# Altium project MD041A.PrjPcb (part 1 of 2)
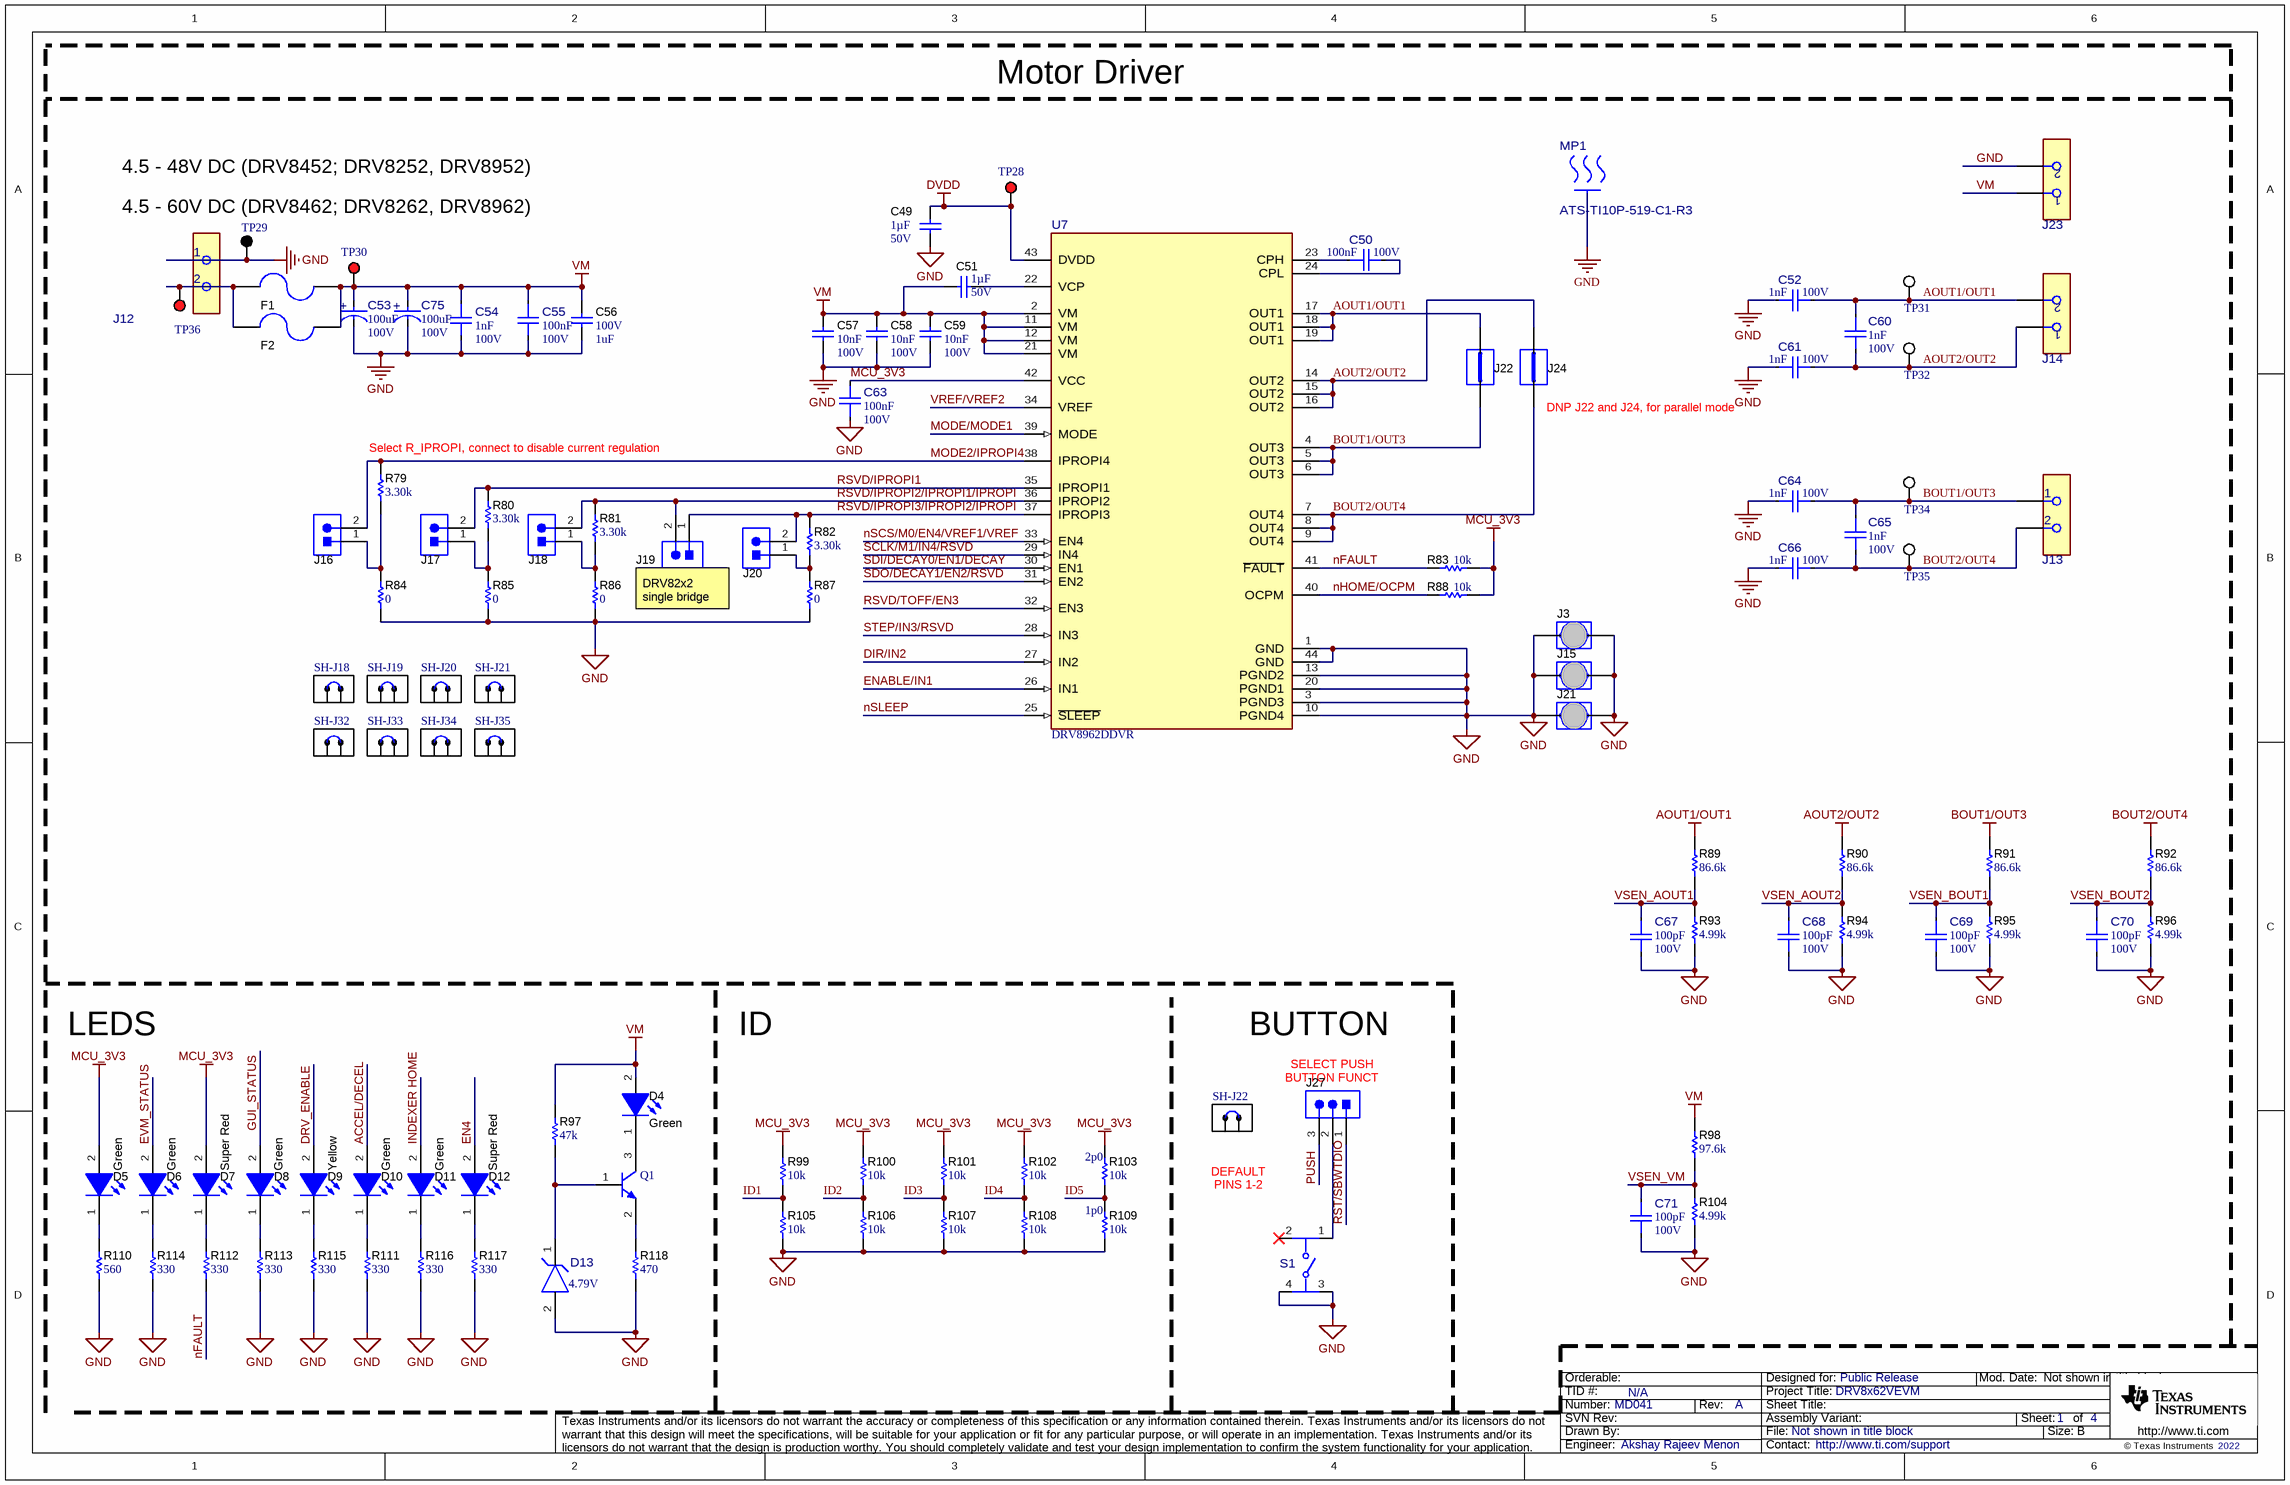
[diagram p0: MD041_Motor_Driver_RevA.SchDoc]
CopyrightYear: 2022; PCB_Layout: Jacob Thompson; PCB_Rev: A; PRJ_Customer: Public Release; PRJ_Engineer: Akshay Rajeev Menon; PRJ_Number: MD041; PRJ_Title: DRV8x62VEVM; SCH_Rev: A; TechSupport: http://www.ti.com/support; TID: N/A
4 sheets, 346 parts. Net scope: global (net labels, ports and power ports of the same name join across sheets).
Board file: MD041A.PcbDoc
Sheets:
  MD041_Motor_Driver_RevA.SchDoc
  MD041_ezFET_RevA.SchDoc
  MD041_Motor_control_RevA.SchDoc
  MD041_Hardware_RevA.SchDoc

## Sheet MD041_Motor_Driver_RevA.SchDoc
size 431 x 279 mm; Date: Not shown in title block; ApprovedBy: Not shown in title block; CheckedBy: Not shown in title block; Author: Not shown in title block; CompanyName: Not shown in title block; Engineer: Not shown in title block; Organization: Not shown in title block; Address1: Not shown in title block; Address2: Not shown in title block; Address3: Not shown in title block; Address4: Not shown in title block; DocumentNumber: 2; Revision: Use project parameter SCH_Rev; SheetNumber: 1; SheetTotal: 4; PageSetup: Record=PageOptions¦CenterHorizontal=True¦CenterVertical=True¦PrintScale=1.00¦XCorrection=1.00¦YCorrection=1.00¦PrintKind=0¦BorderSize=5000000¦LeftOffset=0¦BottomOffset=0¦Orientation=2¦PaperLength=1000¦PaperWidth=1000¦Scale=100¦PaperSource=15¦PrintQuality=600¦MediaType=1¦DitherType=10¦PaperKind=Letter¦PrintScaleMode=1

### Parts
C49  Cap_F: 1µF  VDC_V: 50V  [0805_HV]  (hidden comment: C2012X7R1H105K125AB)
C50  Cap_F: 100nF  VDC_V: 100V  [FP-885012206120_0603-MFG]  (hidden comment: 885012206120)
C51  Cap_F: 1µF  VDC_V: 50V  [0805_HV]  (hidden comment: C2012X7R1H105K125AB)
C52  ValueDisplayed: 1nF  VDC_V: 100V  [FP-885012006085_0603-MFG]  (hidden comment: 885012006085)
C53  ValueDisplayed: 100uF  VDC_V: 100V  [FP-EMVY101ARA101MKE0S_RADIAL-MFG]  (hidden comment: EMVY101ARA101MKE0S)
C54  ValueDisplayed: 1nF  VDC_V: 100V  [FP-885012006085_0603-MFG]  (hidden comment: 885012006085)
C55  Cap_F: 100nF  VDC_V: 100V  [FP-885012206120_0603-MFG]  (hidden comment: 885012206120)
C56  VDC_V: 100V  ValueDisplayed: 1uF  [1210_220]  (hidden comment: CGA6M2X7R2A105K200AA)
C57  Cap_F: 10nF  VDC_V: 100V  [0603L]  (hidden comment: 885012206114)
C58  Cap_F: 10nF  VDC_V: 100V  [0603L]  (hidden comment: 885012206114)
C59  Cap_F: 10nF  VDC_V: 100V  [0603L]  (hidden comment: 885012206114)
C60  ValueDisplayed: 1nF  VDC_V: 100V  [FP-885012006085_0603-MFG]  (hidden comment: 885012006085)
C61  ValueDisplayed: 1nF  VDC_V: 100V  [FP-885012006085_0603-MFG]  (hidden comment: 885012006085)
C63  Cap_F: 100nF  VDC_V: 100V  [FP-885012206120_0603-MFG]  (hidden comment: 885012206120)
C64  ValueDisplayed: 1nF  VDC_V: 100V  [FP-885012006085_0603-MFG]  (hidden comment: 885012006085)
C65  ValueDisplayed: 1nF  VDC_V: 100V  [FP-885012006085_0603-MFG]  (hidden comment: 885012006085)
C66  ValueDisplayed: 1nF  VDC_V: 100V  [FP-885012006085_0603-MFG]  (hidden comment: 885012006085)
C67  ValueDisplayed: 100pF  VDC_V: 100V  [FP-885012005080_0402-MFG]  (hidden comment: 885012005080)
C68  ValueDisplayed: 100pF  VDC_V: 100V  [FP-885012005080_0402-MFG]  (hidden comment: 885012005080)
C69  ValueDisplayed: 100pF  VDC_V: 100V  [FP-885012005080_0402-MFG]  (hidden comment: 885012005080)
C70  ValueDisplayed: 100pF  VDC_V: 100V  [FP-885012005080_0402-MFG]  (hidden comment: 885012005080)
C71  ValueDisplayed: 100pF  VDC_V: 100V  [FP-885012005080_0402-MFG]  (hidden comment: 885012005080)
C75  ValueDisplayed: 100uF  VDC_V: 100V  [FP-EMVY101ARA101MKE0S_RADIAL-MFG]  (hidden comment: EMVY101ARA101MKE0S)
D4  value Green  [WL-SMCW_GREEN]  (hidden comment: 150060VS75000)
D5  value Green  [WL-SMCW_GREEN]  (hidden comment: 150060VS75000)
D6  value Green  [WL-SMCW_GREEN]  (hidden comment: 150060VS75000)
D7  value Super Red  [WL-SMCW_RED]  (hidden comment: 150060SS75000)
D8  value Green  [WL-SMCW_GREEN]  (hidden comment: 150060VS75000)
D9  value Yellow  [WL-SMCW_YELLOW]  (hidden comment: 150060YS75000)
D10  value Green  [WL-SMCW_GREEN]  (hidden comment: 150060VS75000)
D11  value Green  [WL-SMCW_GREEN]  (hidden comment: 150060VS75000)
D12  value Super Red  [WL-SMCW_RED]  (hidden comment: 150060SS75000)
D13  Vf_V: 4.79V  [FP-BZX84J-B4V7,115_SC90-MFG]  (hidden comment: BZX84J-B4V7,115)
F1  0463015.ER  [Fuse_0463]  (value not drawn)
F2  0463015.ER  [Fuse_0463]  (value not drawn)
J3  D3082-05  [Harwin_D3082-05]  (value not drawn)
J12  691256610002  [FP-691256610002_HDR2-MFG]  (value not drawn)
J13  691250610002  [FP-691250610002_CONN_TERM_BLOCK2-MFG]  (value not drawn)
J14  691250610002  [FP-691250610002_CONN_TERM_BLOCK2-MFG]  (value not drawn)
J15  D3082-05  [Harwin_D3082-05]  (value not drawn)
J16  PBC02SAAN  [Sullins_PBC02SAAN]  (value not drawn)
J17  PBC02SAAN  [Sullins_PBC02SAAN]  (value not drawn)
J18  PBC02SAAN  [Sullins_PBC02SAAN]  (value not drawn)
J19  PBC02SAAN  [Sullins_PBC02SAAN]  (value not drawn)
J20  PBC02SAAN  [Sullins_PBC02SAAN]  (value not drawn)
J21  D3082-05  [Harwin_D3082-05]  (value not drawn)
J22  D3082-05  [Harwin_D3082-05]  (value not drawn)
J23  691250610002  [FP-691250610002_CONN_TERM_BLOCK2-MFG]  (value not drawn)
J24  D3082-05  [Harwin_D3082-05]  (value not drawn)
J27  61300311121  [WURTH_61300311121]  (value not drawn)
MP1  ATS-TI10P-519-C1-R3  [FP-ATS-TI10P-519-C1-R3_HEAT_SINK-MFG]
Q1  BC846BLT1G  [ONSC-SOT-23-3-318-08_V]  (value not drawn)
R79  ValueDisplayed: 3.30k  [0402L]  (hidden comment: ERJ-2RKF3301X)
R80  ValueDisplayed: 3.30k  [0402L]  (hidden comment: ERJ-2RKF3301X)
R81  ValueDisplayed: 3.30k  [0402L]  (hidden comment: ERJ-2RKF3301X)
R82  ValueDisplayed: 3.30k  [0402L]  (hidden comment: ERJ-2RKF3301X)
R83  ValueDisplayed: 10k  [0603L]  (hidden comment: RC0603JR-0710KL)
R84  ValueDisplayed: 0  [0402]  (hidden comment: CRCW04020000Z0EDHP)
R85  ValueDisplayed: 0  [0402]  (hidden comment: CRCW04020000Z0EDHP)
R86  ValueDisplayed: 0  [0402]  (hidden comment: CRCW04020000Z0EDHP)
R87  ValueDisplayed: 0  [0402]  (hidden comment: CRCW04020000Z0EDHP)
R88  ValueDisplayed: 10k  [0603L]  (hidden comment: RC0603JR-0710KL)
R89  ValueDisplayed: 86.6k  [0603L]  (hidden comment: CRCW060386K6FKEA)
R90  ValueDisplayed: 86.6k  [0603L]  (hidden comment: CRCW060386K6FKEA)
R91  ValueDisplayed: 86.6k  [0603L]  (hidden comment: CRCW060386K6FKEA)
R92  ValueDisplayed: 86.6k  [0603L]  (hidden comment: CRCW060386K6FKEA)
R93  ValueDisplayed: 4.99k  [0603L]  (hidden comment: CRCW06034K99FKEA)
R94  ValueDisplayed: 4.99k  [0603L]  (hidden comment: CRCW06034K99FKEA)
R95  ValueDisplayed: 4.99k  [0603L]  (hidden comment: CRCW06034K99FKEA)
R96  ValueDisplayed: 4.99k  [0603L]  (hidden comment: CRCW06034K99FKEA)
R97  ValueDisplayed: 47k  [0402]  (hidden comment: CRCW040247K0JNED)
R98  ValueDisplayed: 97.6k  [0603]  (hidden comment: CRCW060397K6FKEA)
R99  ValueDisplayed: 10k  [0603L]  (hidden comment: RC0603JR-0710KL)
R100  ValueDisplayed: 10k  [0603L]  (hidden comment: RC0603JR-0710KL)
R101  ValueDisplayed: 10k  [0603L]  (hidden comment: RC0603JR-0710KL)
R102  ValueDisplayed: 10k  [0603L]  (hidden comment: RC0603JR-0710KL)
R103  ValueDisplayed: 10k  [0603L]  (hidden comment: RC0603JR-0710KL)
R104  ValueDisplayed: 4.99k  [0603L]  (hidden comment: CRCW06034K99FKEA)
R105  ValueDisplayed: 10k  [0603L]  (hidden comment: RC0603JR-0710KL)
R106  ValueDisplayed: 10k  [0603L]  (hidden comment: RC0603JR-0710KL)
R107  ValueDisplayed: 10k  [0603L]  (hidden comment: RC0603JR-0710KL)
R108  ValueDisplayed: 10k  [0603L]  (hidden comment: RC0603JR-0710KL)
R109  ValueDisplayed: 10k  [0603L]  (hidden comment: RC0603JR-0710KL)
R110  ValueDisplayed: 560  [0603]  (hidden comment: RC0603FR-07560RL)
R111  ValueDisplayed: 330  [0603L]  (hidden comment: Resistor)
R112  ValueDisplayed: 330  [0603L]  (hidden comment: Resistor)
R113  ValueDisplayed: 330  [0603L]  (hidden comment: Resistor)
R114  ValueDisplayed: 330  [0603L]  (hidden comment: Resistor)
R115  ValueDisplayed: 330  [0603L]  (hidden comment: Resistor)
R116  ValueDisplayed: 330  [0603L]  (hidden comment: Resistor)
R117  ValueDisplayed: 330  [0603L]  (hidden comment: Resistor)
R118  ValueDisplayed: 470  [0603]  (hidden comment: RC0603FR-07470RL)
S1  430481025816  [FP-430481025816_SMT_SW_6MM2_6MM2-MFG]  (value not drawn)
SH-J18  60900213421  [Wurth_60900213421]  (value not drawn)
SH-J19  60900213421  [Wurth_60900213421]  (value not drawn)
SH-J20  60900213421  [Wurth_60900213421]  (value not drawn)
SH-J21  60900213421  [Wurth_60900213421]  (value not drawn)
SH-J22  60900213421  [Wurth_60900213421]  (value not drawn)
SH-J32  60900213421  [Wurth_60900213421]  (value not drawn)
SH-J33  60900213421  [Wurth_60900213421]  (value not drawn)
SH-J34  60900213421  [Wurth_60900213421]  (value not drawn)
SH-J35  60900213421  [Wurth_60900213421]  (value not drawn)
TP28  5010  [Keystone5010]  (value not drawn)
TP29  5011  [Keystone5011]  (value not drawn)
TP30  5010  [Keystone5010]  (value not drawn)
TP31  5015  [Testpoint_Keystone_Miniature]  (value not drawn)
TP32  5015  [Testpoint_Keystone_Miniature]  (value not drawn)
TP34  5015  [Testpoint_Keystone_Miniature]  (value not drawn)
TP35  5015  [Testpoint_Keystone_Miniature]  (value not drawn)
TP36  5010  [Keystone5010]  (value not drawn)
U7  DRV8962DDVR  [DDV0044E-MFG]

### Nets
AOUT1/OUT1: C52.2 C60.1 J14.2 J22.2 R89.2 TP31.1 U7.17(OUT1) U7.18(OUT1) U7.19(OUT1)
AOUT2/OUT2: C60.2 C61.2 J14.1 J24.2 R90.2 TP32.1 U7.14(OUT2) U7.15(OUT2) U7.16(OUT2)
BOUT1/OUT3: C64.2 C65.1 J13.1 J22.1 R91.2 TP34.1 U7.4(OUT3) U7.5(OUT3) U7.6(OUT3)
BOUT2/OUT4: C65.2 C66.2 J13.2 J24.1 R92.2 TP35.1 U7.7(OUT4) U7.8(OUT4) U7.9(OUT4)
DVDD: C49.2 TP28.1 U7.43(DVDD)
GND: C49.1 C52.1 C53.1(CATHODE) C54.2 C55.2 C56.2 C57.2 C58.2 C59.2 C61.1 C63.1 C64.1 C66.1 C67.2 C68.2 C69.2 C70.2 C71.2 C75.1(CATHODE) D13.2(anode) J3.1 J3.2 J12.1 J15.1 J15.2 J21.1 J21.2 J23.2 R84.1 R85.1 R86.1 R87.1 R93.1 R94.1 R95.1 R96.1 R104.1 R105.2 R106.2 R107.2 R108.2 R109.2 R110.1 R111.1 R113.1 R114.1 R115.1 R116.1 R117.1 R118.1 S1.3 S1.4 TP29.1 U7.1(GND) U7.3(PGND3) U7.10(PGND4) U7.13(PGND2) U7.20(PGND1) U7.44(GND)
MCU_3V3: C63.2 D5.2(A) D7.2(A) R83.2 R88.2 R99.1 R100.1 R101.1 R102.1 R103.1 U7.42(VCC)
VM: C51.2 C53.2(ANODE) C54.1 C55.1 C56.1 C57.1 C58.1 C59.1 C75.2(ANODE) D4.2(A) F1.1 F2.1 J23.1 R97.2 R98.2 TP30.1 U7.2(VM) U7.11(VM) U7.12(VM) U7.21(VM)
ACCEL/DECEL: D10.2(A)
DIR/IN2: U7.27(IN2)
DRV_ENABLE: D9.2(A)
EN4: D12.2(A)
ENABLE/IN1: U7.26(IN1)
EVM_STATUS: D6.2(A)
GUI_STATUS: D8.2(A)
ID1: R99.2 R105.1
ID2: R100.2 R106.1
ID3: R101.2 R107.1
ID4: R102.2 R108.1
ID5: R103.2 R109.1
INDEXER HOME: D11.2(A)
MODE2/IPROPI4: J16.2 R79.2 U7.38(IPROPI4)
MODE/MODE1: U7.39(MODE)
nFAULT: R83.1 R112.1 U7.41(~{FAULT})
nHOME/OCPM: R88.1 U7.40(OCPM)
nSCS/M0/EN4/VREF1/VREF: U7.33(EN4)
nSLEEP: U7.25(~{SLEEP})
PUSH: J27.3
RST/SBWTDIO: J27.1
RSVD/IPROPI1: J17.2 R80.2 U7.35(IPROPI1)
RSVD/IPROPI2/IPROPI1/IPROPI: J18.2 J19.2 R81.2 U7.36(IPROPI2)
RSVD/IPROPI3/IPROPI2/IPROPI: J19.1 J20.2 R82.2 U7.37(IPROPI3)
RSVD/TOFF/EN3: U7.32(EN3)
SCLK/M1/IN4/RSVD: U7.29(IN4)
SDI/DECAY0/EN1/DECAY: U7.30(EN1)
SDO/DECAY1/EN2/RSVD: U7.31(EN2)
STEP/IN3/RSVD: U7.28(IN3)
VREF/VREF2: U7.34(VREF)
VSEN_AOUT1: C67.1 R89.1 R93.2
VSEN_AOUT2: C68.1 R90.1 R94.2
VSEN_BOUT1: C69.1 R91.1 R95.2
VSEN_BOUT2: C70.1 R92.1 R96.2
VSEN_VM: C71.1 R98.1 R104.2
NetC50_1: C50.1 U7.23(CPH)
NetC50_2: C50.2 U7.24(CPL)
NetC51_1: C51.1 U7.22(VCP)
NetD4_1: D4.1(K) Q1.3(C)
NetD5_1: D5.1(K) R110.2
NetD6_1: D6.1(K) R114.2
NetD7_1: D7.1(K) R112.2
NetD8_1: D8.1(K) R113.2
NetD9_1: D9.1(K) R115.2
NetD10_1: D10.1(K) R111.2
NetD11_1: D11.1(K) R116.2
NetD12_1: D12.1(K) R117.2
NetD13_1: D13.1(cathode) Q1.1(B) R97.1
NetF1_2: F1.2 F2.2 J12.2 TP36.1
NetJ16_1: J16.1 R79.1 R84.2
NetJ17_1: J17.1 R80.1 R85.2
NetJ18_1: J18.1 R81.1 R86.2
NetJ20_1: J20.1 R82.1 R87.2
NetJ27_2: J27.2 S1.1
NetQ1_2: Q1.2(E) R118.2

Not connected (* = marked no-connect by the designer): S1 2*

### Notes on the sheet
- Motor Driver
- 4.5 - 48V DC (DRV8452; DRV8252, DRV8952)
- 4.5 - 60V DC (DRV8462; DRV8262, DRV8962)
- (near J24) DNP J22 and J24, for parallel mode
- (near R79) Select R_IPROPI, connect to disable current regulation
- DRV82x2 single bridge
- LEDS
- ID
- BUTTON
- (near J27) SELECT PUSH
- (near J27) BUTTON FUNCT
- (near R103) 2p0
- (near SH-J22) DEFAULT
- (near R109) 1p0
- PINS 1-2

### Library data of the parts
C49 C51 = CMP-0007873-2: CAP, CERM, 1 uF, 50 V, +/- 10%, X7R, 0805; Manufacturer: TDK; TaMin_C: -55°C; ESR_ohm: 8.782m; Polarized: N; SizeAreaWB_mm2: 6.75; Value1: 0.008782 ohm; U/M: EA; Value: 1uF; TaMax_C: 125°C; SizeZ_mm: 1.45; SizeX_mm: 2; SizeY_mm: 1.25; Cap_Case: 0805; SizeArea_mm2: 2.5; IRMS_A: 2.2049A; AEC Category: Q200
C50 C55 C63 = CMP-0095152-1: 0.1 µF ±10% 100V Ceramic Capacitor X7R 0603 (1608 Metric); Manufacturer: Wurth Electronics; Value: 100nF; SizeZ_mm: 0.87mm; AEC Qualified: No; TempCo: 15%
C52 C54 C60 C61 C64-C66 = CMP-0097311-1: 1000 pF ±5% 100V Ceramic Capacitor C0G, NP0 0603 (1608 Metric); Manufacturer: Wurth Electronics; TempCo: 30ppm/°C; SizeZ_mm: 0.87mm; AEC Qualified: No; Value: 1nF
C53 C75 = CMP-0094051-1: 100uF 100V 20% Aluminum Electrolytic Capacitors Radial, Can - SMD - 5000 Hrs @ 105°C; Manufacturer: United Chemi-Con; Value: 100µF; IRMS_A: 450mA; Life: 5000Hours; SizeZ_mm: 14mm; AEC Grade: Grade 2; Leakage Current: 100uA; Dissipation Factor: 10%; AEC Qualified: Yes
C56 = CMP-0009145-2: CAP, CERM, 1 uF, 100 V, +/- 10%, X7R, AEC-Q200 Grade 1, 1210; Manufacturer: TDK; TaMin_C: -55°C; ESR_ohm: 4.956m; Polarized: N; SizeAreaWB_mm2: 14.7; Value1: 0.004956 ohm; U/M: EA; Value: 1uF; TaMax_C: 125°C; SizeZ_mm: 2.2; SizeX_mm: 3.2; SizeY_mm: 2.5; SizeArea_mm2: 8; AEC Qualified: Y; Cap_F: 1µF; IRMS_A: 3.3073A; AEC Grade: 1; AEC Category: Q200
C57-C59 = CMP-0079993-1: CAP, CERM, 0.01 µF, 100 V,+/- 10%, X7R, 0603; Manufacturer: Wurth Elektronik; Polarized: N; Value: 0.01uF; ValueDisplayed: 0.01µF; U/M: EA; TaMin_C: -55°C; TaMax_C: 105°C; Cap_Case: 0603; SizeX_mm: 1.6; SizeArea_mm2: 1.28; AEC Category: Q200; SizeZ_mm: 1; SizeAreaWB_mm2: 4.68; SizeY_mm: 0.8
C67-C71 = CMP-0097308-1: 100 pF ±5% 100V Ceramic Capacitor C0G, NP0 0402 (1005 Metric); Manufacturer: Wurth Electronics; Value: 100pF; SizeZ_mm: 0.55mm; TempCo: 30ppm/°C; AEC Qualified: No
D4-D6 D8 D10 D11 = CMP-0002894-2: LED, Green, SMD; Manufacturer: Wurth Elektronik; Type: AlInGaP; Value2: 2V; Io_A: 20mA; Value1: W
D7 D12 = CMP-0002893-1: LED, Super Red, SMD; Manufacturer: Wurth Elektronik; Io_A: 20mA; Value1: W; U/M: EA; Vf_V: 1.9V; Type: AlInGaP
D9 = CMP-0002892-3: LED, Yellow, SMD; Manufacturer: Wurth Elektronik; Value1: W; Vf_V: 2V; Type: AlInGaP; Io_A: 20mA
D13 = CMP-0097377-1: Diode Zener Single 4.7V 2% 550mW Automotive 2-Pin SOD-323F T/R; Manufacturer: Nexperia; TaMin_C: -55°C; Vr_V: 2V; SizeZ_mm: 0.8mm; Max Reverse Leakage Current: 3uA; TJmax_C: 150°C; Zener Impedance: 80Ω; AEC Grade: Grade 0; Forward Current: 250mA; TaMax_C: +150°C; AEC Qualified: Yes
F1 F2 = CMP-0081016-1: Fuse, 15 A, 250 VAC, 100 VDC, SMD; Manufacturer: Littelfuse; TaMin_C: -55°C; Irating_A: 15A; SizeAreaWB_mm2: 61.952; Interrupt_AC: 100A; Interrupt_DC: 50A; VAC_V: 250V; TaMax_C: 125°C; Fuse Speed: Fast; SizeZ_mm: 3.12; SizeX_mm: 10.1; SizeArea_mm2: 31.512; VDC_V: 100V; Fuse Technology: Board Mount; Rtyp_Ohm: 4.7m; MeltingTyp: 142
J3 J15 J21 J22 J24 = CMP-0075110-1: 1mm Uninsulated Shorting Plug, 10.16mm spacing, TH; Manufacturer: Harwin; CNHeader: False; Green_Lifecycle: Active; Green_REACh: Passed; CompType: Jumper Wire
J12 = CMP-0086764-1: 2 Position Wire to Board Terminal Block Horizontal with Board 0.400" (10.16mm) Through Hole; Manufacturer: Wurth; Current_A: 57A; Voltage_V: 750V; ContactFinish: Zinc; Row_Count: 1
J13 J14 J23 = CMP-0093233-2: 2 Position Wire to Board Terminal Block Horizontal with Board 0.250" (6.35mm) Through Hole; Manufacturer: Wurth Electronics; Current_A: 32A; Conn Gender: Female; Row_Count: 1; ContactFinish: Zinc; SizeZ_mm: 21.6mm; Max Wire Gauge: 10; Min Wire Gauge: 30; Voltage_V: 450V; AEC Qualified: No; Is Female: yes
J16-J20 = CMP-0054566-1: Header, 100mil, 2x1, Gold, TH; Manufacturer: Sullins Connector Solutions; CNHeader: TRUE; Current_A: 3A; Green_Lifecycle: Active; Shrouded: N; Gender: Male; Green_REACh: Passed; Voltage_V: 1.8kV; Row_Count: 1; Pitch_mm: 2.54; CT: FALSE; Cert_UL: Y
J27 = CMP-0054796-4: Header, 2.54 mm, 3x1, Gold, TH; Manufacturer: Wurth Elektronik; Green_Lifecycle: Active; Green_REACh: Passed; CT: FALSE; CNHeader: TRUE
MP1 = CMP-0096184-1: Heat Sink Aluminum Top Mount; Manufacturer: Advanced Thermal Solutions; AEC Qualified: No; Thermal Resistance Forced Air Flow: 2.2°C/W; SizeZ_mm: 35.6mm; Standoff Height: 1.6mm
Q1 = CMP-1048-00779-1: General Purpose Transistor, NPN Silicon, 3-Pin SOT-23, Pb-Free, Tape and Reel; Manufacturer: On Semiconductor; fT Min (MHz): 100; IC Continuous (A): 0.1
R79-R82 = CMP-0026695-1: RES, 3.30 k, 1%, 0.1 W, AEC-Q200 Grade 0, 0402; Manufacturer: Panasonic; Power_W: 100mW; TempCo: 100 ppm/C; Value_Code: 3k30; U/M: EA; Value: 3.30k; Res_ohm: 3.3k; SizeX_mm: 1; SizeY_mm: 0.5; SizeZ_mm: 0.6; Value2: 0.1W; AEC Qualified: Y; VDC_V: 50V; AEC Grade: 0; AEC Category: Q200
R83 R88 R99-R103 R105-R109 = CMP-0025886-5: RES, 10 k, 5%, 0.1 W, 0603; Manufacturer: Yageo; Power_W: 100mW; TempCo: 100 ppm/C; Value_Code: 10k0; Value: 10k; EIA_Code: E24; SizeX_mm: 1.6; SizeY_mm: 0.8; SizeZ_mm: 1; Value2: 0.1W; SizeArea_mm2: 1.28; AEC Qualified: N; VDC_V: 75V; AEC Category: Q200; SizeAreaWB_mm2: 4.68
R84-R87 = CMP-0081856-1: RES, 0, 0%, 0.2 W, AEC-Q200 Grade 0, 0402; Manufacturer: Vishay-Dale; SizeAreaWB_mm2: 3; SizeArea_mm2: 0.5; AEC Qualified: Y; AEC Category: Q200; Value: 0; SizeZ_mm: 0.6; Power_W: 200mW; VDC_V: 50V; Value2: 0.2W; SizeX_mm: 1
R89-R92 = CMP-0022628-4: RES, 86.6 k, 1%, 0.1 W, AEC-Q200 Grade 0, 0603; Manufacturer: Vishay-Dale; Value: 86.6k; Value_Code: 86k6; Power_W: 100mW; Value2: 0.1W; VDC_V: 75V; TempCo: 100 ppm/C; EIA_Code: E96; AEC Category: Q200; AEC Qualified: Y; AEC Grade: 0; SizeY_mm: 0.8; SizeZ_mm: 1; SizeArea_mm2: 1.28; SizeX_mm: 1.6
R93-R96 R104 = CMP-0022458-4: RES, 4.99 k, 1%, 0.1 W, AEC-Q200 Grade 0, 0603; Manufacturer: Vishay-Dale; Value: 4.99k; Value_Code: 4k99; Power_W: 100mW; Value2: 0.1W; VDC_V: 75V; TempCo: 100 ppm/C; EIA_Code: E96; SizeX_mm: 1.6; SizeY_mm: 0.8; SizeZ_mm: 1; SizeArea_mm2: 1.28; AEC Qualified: Y; AEC Category: Q200; AEC Grade: 0
R97 = CMP-0026935-3: RES, 47 k, 5%, 0.063 W, AEC-Q200 Grade 0, 0402; Manufacturer: Vishay-Dale; Power_W: 63mW; TempCo: 200 ppm/C; Value_Code: 47k0; Value: 47k; EIA_Code: E24; SizeX_mm: 1; SizeY_mm: 0.5; SizeZ_mm: 0.6; Value2: 0.063W; AEC Qualified: Y; VDC_V: 50V; AEC Category: Q200; AEC Grade: 0
R98 = CMP-0022663-4: RES, 97.6 k, 1%, 0.1 W, AEC-Q200 Grade 0, 0603; Manufacturer: Vishay-Dale; Value: 97.6k; Value_Code: 97k6; Power_W: 100mW; Value2: 0.1W; VDC_V: 75V; TempCo: 100 ppm/C; EIA_Code: E96; AEC Category: Q200; AEC Qualified: Y; AEC Grade: 0; SizeY_mm: 0.8; SizeZ_mm: 1; SizeArea_mm2: 1.28; SizeX_mm: 1.6
R110 = CMP-0023183-5: RES, 560, 1%, 0.1 W, 0603; Manufacturer: Yageo; Power_W: 100mW; TempCo: 100 ppm/C; Value_Code: 560R; Value: 560; SizeX_mm: 1.6; SizeY_mm: 0.8; SizeZ_mm: 1; Value2: 0.1W; SizeArea_mm2: 1.28; AEC Qualified: N; VDC_V: 75V; AEC Category: Q200; SizeAreaWB_mm2: 4.68
R111-R117 = CMP-0025785-4: RES, 330, 5%, 0.1 W, AEC-Q200 Grade 0, 0603; PartNumber: CRCW0603330RJNEA; Manufacturer: Vishay-Dale; Value: 330; Value_Code: 330R; Power_W: 100mW; Value2: 0.1W; VDC_V: 75V; TempCo: 200 ppm/C; EIA_Code: E24; AEC Category: Q200; AEC Qualified: Y; AEC Grade: 0; SizeX_mm: 1.6; SizeY_mm: 0.8; SizeZ_mm: 1; SizeArea_mm2: 1.28
R118 = CMP-0023129-5: RES, 470, 1%, 0.1 W, 0603; Manufacturer: Yageo; Power_W: 100mW; TempCo: 100 ppm/C; Value_Code: 470R; Value: 470; SizeX_mm: 1.6; SizeY_mm: 0.8; SizeZ_mm: 1; Value2: 0.1W; SizeArea_mm2: 1.28; AEC Qualified: N; VDC_V: 75V; AEC Category: Q200; SizeAreaWB_mm2: 4.68
S1 = CMP-0097347-1: Tactile Switch SPST-NO Top Actuated Surface Mount; Manufacturer: Wurth Electronics; VDC_V: 12V; Electromechanical Life: 1000000Cycles; SizeZ_mm: 2.7mm; Coil Resistance_ohm: 100mΩ; Operating Force: 160gf; AEC Qualified: No; Contact Current Rating: 50mA
SH-J18-SH-J22 SH-J32-SH-J35 = CMP-0003761-2: Shunt, 2.54mm, Gold, Black; Manufacturer: Wurth Elektronik
TP28 TP30 TP36 = CMP-0055147-2: Test Point, Multipurpose, Red, TH; Manufacturer: Keystone Electronics; CNHeader: FALSE; Green_Lifecycle: Active; Green_REACh: Passed; ContactFinish: Silver; CT: TRUE
TP29 = CMP-0055148-2: Test Point, Multipurpose, Black, TH; Manufacturer: Keystone Electronics; CNHeader: FALSE; Green_Lifecycle: Active; Green_REACh: Passed; ContactFinish: Silver; CT: TRUE
TP31 TP32 TP34 TP35 = CMP-0055152-2: Test Point, Miniature, SMT; Manufacturer: Keystone Electronics; CNHeader: FALSE; Green_Lifecycle: Active; Green_REACh: Passed; CT: TRUE
U7 = CMP-0094088-3: Quad Half-Bridge Motor Driver with Current Sense Output; Manufacturer: Texas Instruments; Standoff Height: 0.05mm; AEC Qualified: No; CompType: IC; Motor Type: Stepper; SizeZ_mm: 1.2mm; Min Supply Voltage: 4.5V; TaMax_C: +125°C; TaMin_C: -40°C; Max Supply Voltage: 60V; Number Of Outputs: 4; Nominal Supply Current: 3-7mA; TJmax_C: +150°C; Switching Frequency: 360kHz; AEC Category: Q200

## Sheet MD041_ezFET_RevA.SchDoc
size 431 x 279 mm; Date: Not shown in title block; ApprovedBy: Not shown in title block; CheckedBy: Not shown in title block; Author: Not shown in title block; CompanyName: Not shown in title block; Engineer: Not shown in title block; Organization: Not shown in title block; Address1: Not shown in title block; Address2: Not shown in title block; Address3: Not shown in title block; Address4: Not shown in title block; DocumentNumber: 2; Revision: Use project parameter SCH_Rev; SheetNumber: 2; SheetTotal: 4; PageSetup: Record=PageOptions¦CenterHorizontal=True¦CenterVertical=True¦PrintScale=1.00¦XCorrection=1.00¦YCorrection=1.00¦PrintKind=0¦BorderSize=5000000¦LeftOffset=0¦BottomOffset=0¦Orientation=2¦PaperLength=1000¦PaperWidth=1000¦Scale=100¦PaperSource=15¦PrintQuality=600¦MediaType=1¦DitherType=10¦PaperKind=Letter¦PrintScaleMode=1
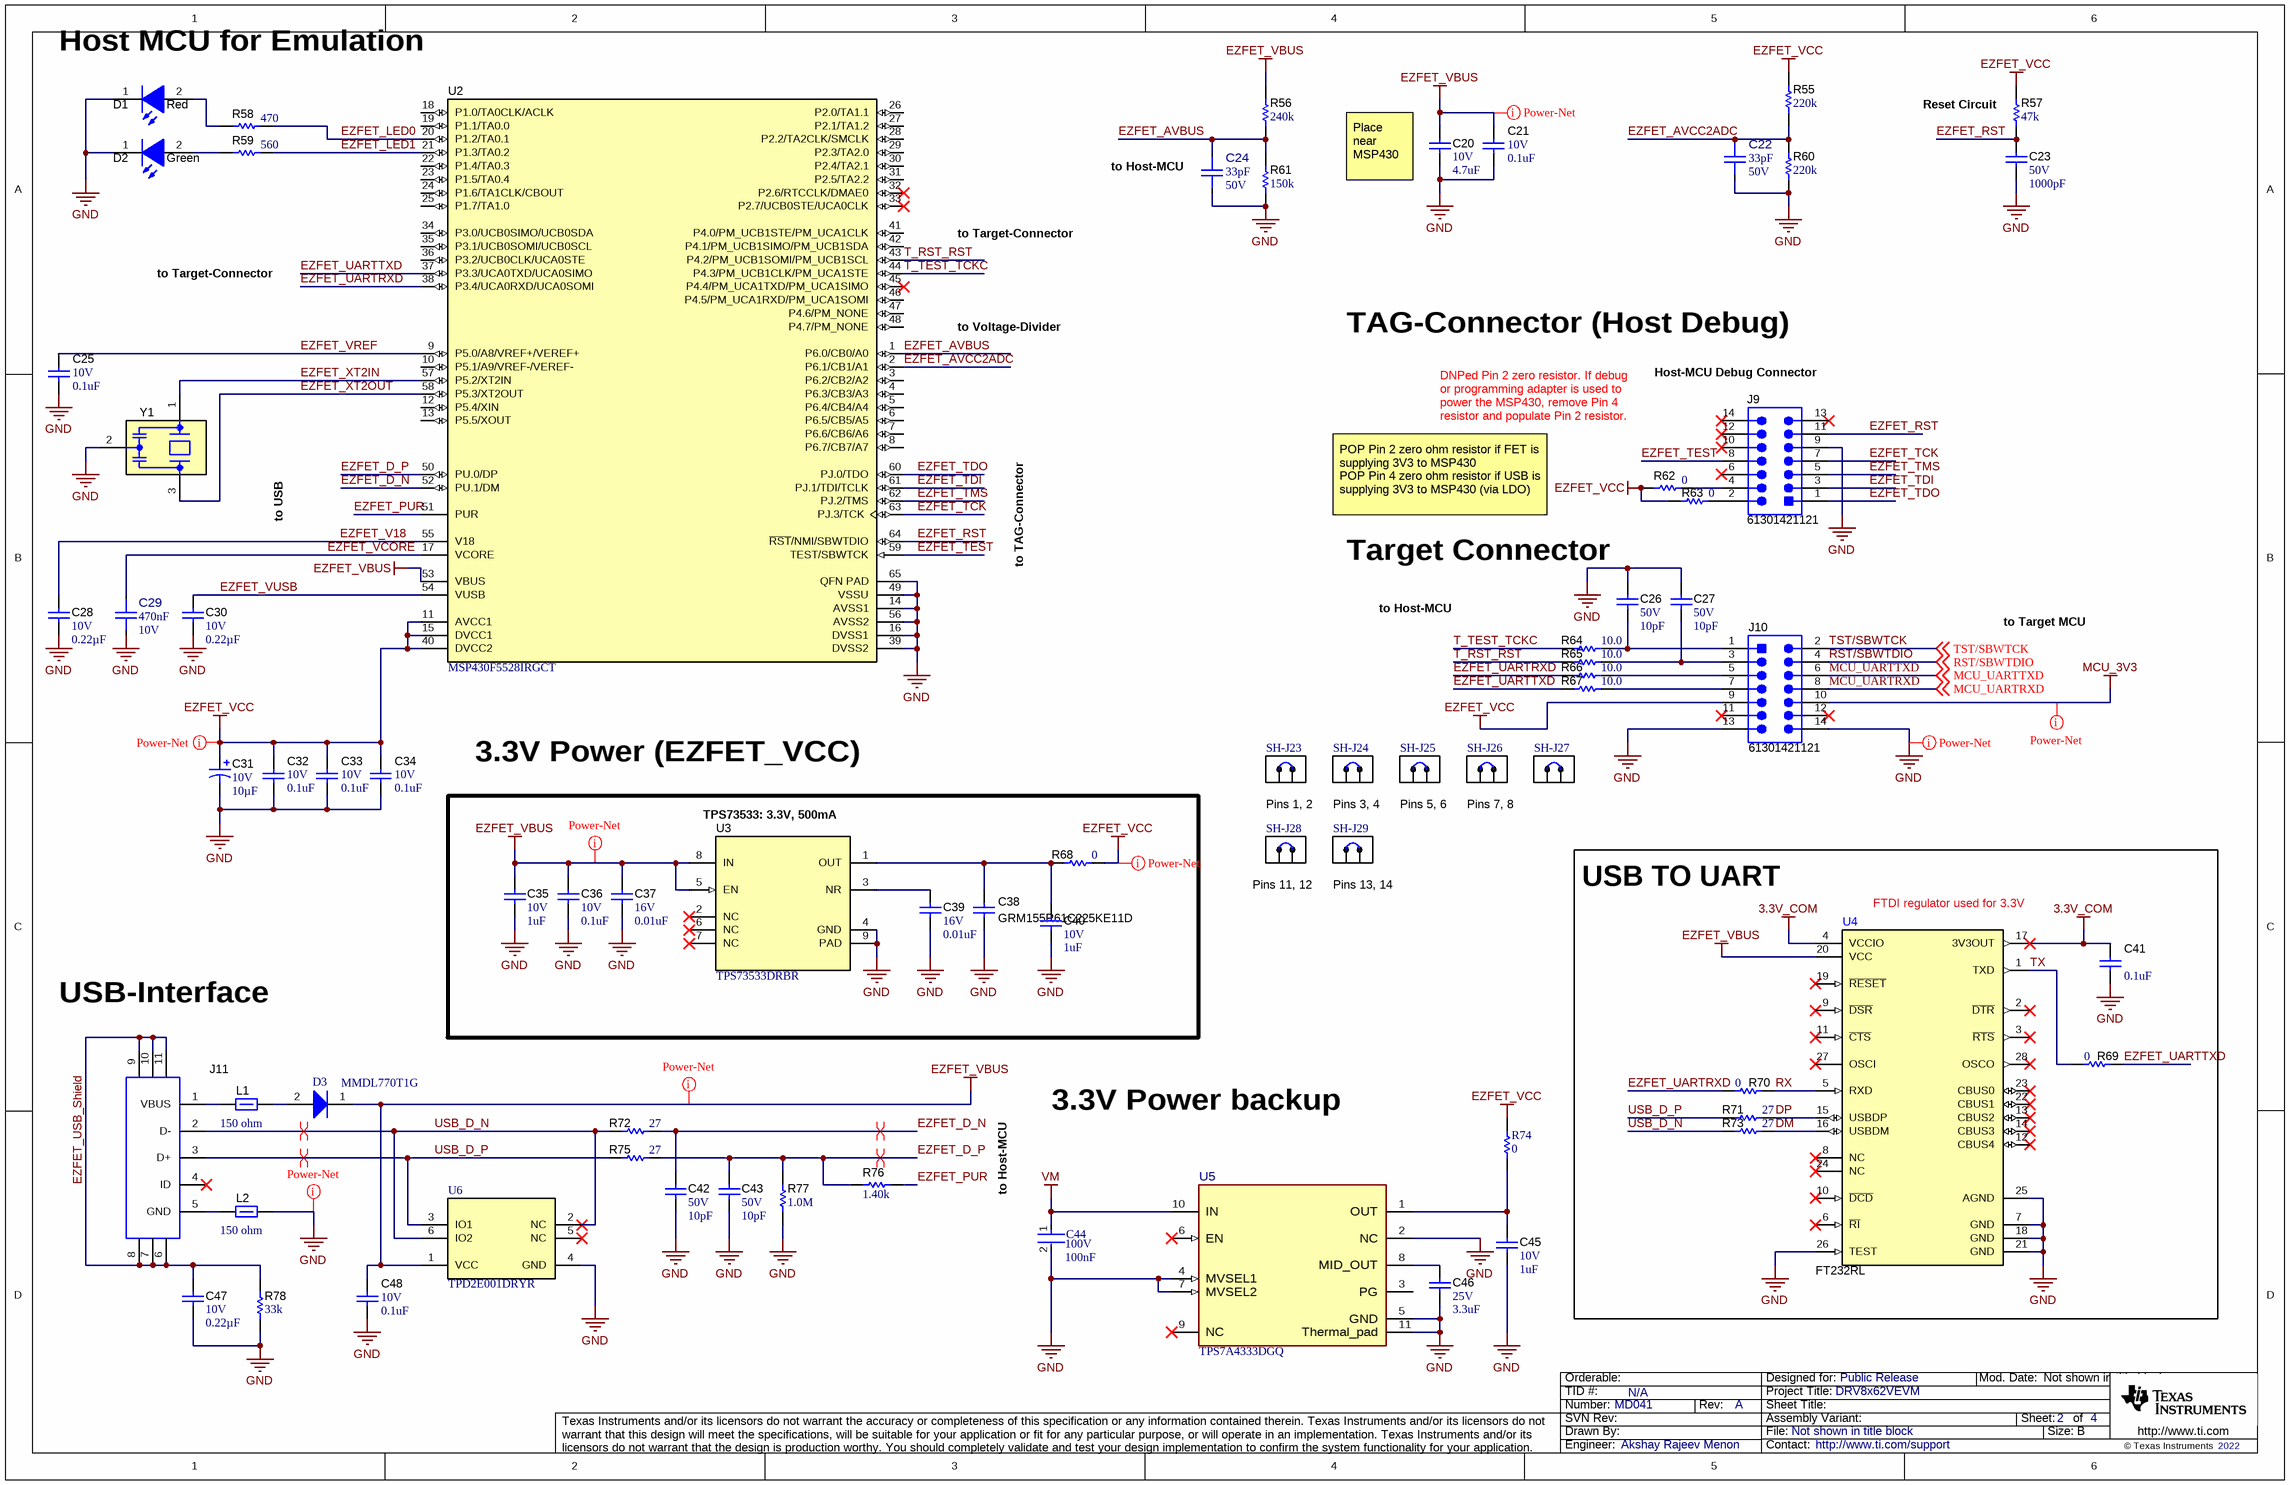
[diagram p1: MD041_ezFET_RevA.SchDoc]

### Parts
C20  VDC_V: 10V  ValueDisplayed: 4.7uF  [0402]  (hidden comment: C1005X5R1A475M050BC)
C21  VDC_V: 10V  ValueDisplayed: 0.1uF  [0402]  (hidden comment: 885012105010)
C22  ValueDisplayed: 33pF  VDC_V: 50V  [FP-885012005058_0402-MFG]  (hidden comment: 885012005058)
C23  VDC_V: 50V  ValueDisplayed: 1000pF  [0402]  (hidden comment: 885012205061)
C24  ValueDisplayed: 33pF  VDC_V: 50V  [FP-885012005058_0402-MFG]  (hidden comment: 885012005058)
C25  VDC_V: 10V  ValueDisplayed: 0.1uF  [0402]  (hidden comment: 885012105010)
C26  VDC_V: 50V  ValueDisplayed: 10pF  [0402]  (hidden comment: 885012005055)
C27  VDC_V: 50V  ValueDisplayed: 10pF  [0402]  (hidden comment: 885012005055)
C28  VDC_V: 10V  ValueDisplayed: 0.22µF  [0402]  (hidden comment: 885012105011)
C29  ValueDisplayed: 470nF  VDC_V: 10V  [FP-885012106008_0603-MFG]  (hidden comment: 885012106008)
C30  VDC_V: 10V  ValueDisplayed: 0.22µF  [0402]  (hidden comment: 885012105011)
C31  VDC_V: 10V  ValueDisplayed: 10µF  [3216-18]  (hidden comment: T520A106M010ATE080)
C32  VDC_V: 10V  ValueDisplayed: 0.1uF  [0402]  (hidden comment: 885012105010)
C33  VDC_V: 10V  ValueDisplayed: 0.1uF  [0402]  (hidden comment: 885012105010)
C34  VDC_V: 10V  ValueDisplayed: 0.1uF  [0402]  (hidden comment: 885012105010)
C35  VDC_V: 10V  ValueDisplayed: 1uF  [0402]  (hidden comment: 885012105012)
C36  VDC_V: 10V  ValueDisplayed: 0.1uF  [0402]  (hidden comment: GRM155R61A104KA01D)
C37  VDC_V: 16V  ValueDisplayed: 0.01uF  [0402]  (hidden comment: GRM155R71C103KA01D)
C38  GRM155R61C225KE11D  [0402]
C39  VDC_V: 16V  ValueDisplayed: 0.01uF  [0402]  (hidden comment: GRM155R71C103KA01D)
C40  VDC_V: 10V  ValueDisplayed: 1uF  [0402]  (hidden comment: 885012105012)
C41  ValueDisplayed: 0.1uF  [0402]  (hidden comment: 885012105010)
C42  VDC_V: 50V  ValueDisplayed: 10pF  [0402]  (hidden comment: 885012005055)
C43  VDC_V: 50V  ValueDisplayed: 10pF  [0402]  (hidden comment: 885012005055)
C44  Voltage Rating: 100V  Capacitance: 100nF  [FP-0603-L_1_6_0_1-W_0_8_0-IPC_B]  (hidden comment: HMK107BJ104MA-T)
C45  VDC_V: 10V  ValueDisplayed: 1uF  [0402]  (hidden comment: 885012105012)
C46  VDC_V: 25V  ValueDisplayed: 3.3uF  [0805_HV]  (hidden comment: GRM21BC81E335KA73L)
C47  VDC_V: 10V  ValueDisplayed: 0.22µF  [0402]  (hidden comment: 885012105011)
C48  VDC_V: 10V  ValueDisplayed: 0.1uF  [0402]  (hidden comment: 885012105010)
D1  value Red  [WL-SMCW_RED]  (hidden comment: 150060RS75000)
D2  value Green  [WL-SMCW_GREEN]  (hidden comment: 150060VS75000)
D3  MMDL770T1G  [ONSC-SOD-323-2-477-02_V]
J9  61301421121  [Wurth_61301421121]
J10  61301421121  [Wurth_61301421121]
J11  1051640001  [Molex_1051640001]  (value not drawn)
L1  value 150 ohm  [0603]  (hidden comment: BLM18AG151BH1D)
L2  ValueDisplayed: 150 ohm  [0603]  (hidden comment: BLM18AG151BH1D)
R55  ValueDisplayed: 220k  [0402]  (hidden comment: RC0402FR-07220KL)
R56  ValueDisplayed: 240k  [0402]  (hidden comment: CRCW0402240KFKED)
R57  ValueDisplayed: 47k  [0402]  (hidden comment: CRCW040247K0JNED)
R58  ValueDisplayed: 470  [0402]  (hidden comment: CRCW0402470RJNED)
R59  ValueDisplayed: 560  [0402]  (hidden comment: CRCW0402560RJNED)
R60  ValueDisplayed: 220k  [0402]  (hidden comment: RC0402FR-07220KL)
R61  ValueDisplayed: 150k  [0402]  (hidden comment: CRCW0402150KFKED)
R62  value 0  [0402L]  (hidden comment: ERJ-2GE0R00X)
R63  value 0  [0402L]  (hidden comment: ERJ-2GE0R00X)
R64  ValueDisplayed: 10.0  [0402]  (hidden comment: CRCW040210R0FKED)
R65  ValueDisplayed: 10.0  [0402]  (hidden comment: CRCW040210R0FKED)
R66  ValueDisplayed: 10.0  [0402]  (hidden comment: CRCW040210R0FKED)
R67  ValueDisplayed: 10.0  [0402]  (hidden comment: CRCW040210R0FKED)
R68  value 0  [0402L]  (hidden comment: Resistor)
R69  value 0  [0603L]  (hidden comment: Resistor)
R70  value 0  [0603L]  (hidden comment: Resistor)
R71  ValueDisplayed: 27  [0402]  (hidden comment: CRCW040227R0JNED)
R72  ValueDisplayed: 27  [0402]  (hidden comment: CRCW040227R0JNED)
R73  ValueDisplayed: 27  [0402]  (hidden comment: CRCW040227R0JNED)
R74  0  [RESC1005X40X25NL05T05]
R75  ValueDisplayed: 27  [0402]  (hidden comment: CRCW040227R0JNED)
R76  ValueDisplayed: 1.40k  [0402]  (hidden comment: CRCW04021K40FKED)
R77  ValueDisplayed: 1.0M  [0402]  (hidden comment: CRCW04021M00JNED)
R78  ValueDisplayed: 33k  [0402]  (hidden comment: CRCW040233K0JNED)
SH-J23  60900213421  [Wurth_60900213421]  (value not drawn)
SH-J24  60900213421  [Wurth_60900213421]  (value not drawn)
SH-J25  60900213421  [Wurth_60900213421]  (value not drawn)
SH-J26  60900213421  [Wurth_60900213421]  (value not drawn)
SH-J27  60900213421  [Wurth_60900213421]  (value not drawn)
SH-J28  60900213421  [Wurth_60900213421]  (value not drawn)
SH-J29  60900213421  [Wurth_60900213421]  (value not drawn)
U2  MSP430F5528IRGCT  [RGC0064B]
U3  TPS73533DRBR  [DRB0008A]
U4  FT232RL  [SSOP28_N]
U5  TPS7A4333DGQ  [DGQ0010E-MFG]
U6  TPD2E001DRYR  [DRY0006A]
Y1  CSTNR4M00GH5L000R0  [MuRata_CSTNR]  (value not drawn)

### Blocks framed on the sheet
TPS73533: 3.3V, 500mA: C35-C40 R68 U3
USB TO UART: C41 R69-R71 R73 U4

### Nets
3.3V_COM: C41.1 U4.4(VCCIO) U4.17(3V3OUT)
EZFET_VBUS: C20.1 C21.1 C35.1 C36.1 C37.1 C48.1 D3.1(K) R56.2 U2.53(VBUS) U3.5(EN) U3.8(IN) U4.20(VCC) U6.1(VCC)
EZFET_VCC: C31.1(+) C32.1 C33.1 C34.1 J10.9 R55.2 R57.2 R62.1 R63.1 R68.2 R74.2 U2.11(AVCC1) U2.15(DVCC1) U2.40(DVCC2)
GND: C20.2 C21.2 C22.2 C23.2 C24.2 C25.2 C26.1 C27.1 C28.2 C29.2 C30.2 C31.2(-) C32.2 C33.2 C34.2 C35.2 C36.2 C37.2 C38.2 C39.2 C40.2 C41.2 C42.2 C43.2 C44.2 C45.2 C46.2 C47.2 C48.2 D1.1(K) D2.1(K) J9.9 J10.13 J10.14 L2.2 R60.1 R61.1 R77.1 R78.1 U2.14(AVSS1) U2.16(DVSS1) U2.39(DVSS2) U2.49(VSSU) U2.56(AVSS2) U2.65(QFN_PAD) U3.4(GND) U3.9(PAD) U4.7(GND) U4.18(GND) U4.21(GND) U4.25(AGND) U4.26(TEST) U5.2(NC) U5.4(MVSEL1) U5.5(GND) U5.7(MVSEL2) U5.11(Thermal_pad) U6.4(GND) Y1.2(GND)
MCU_3V3: J10.10
VM: C44.1 U5.10(IN)
DM: R73.2 U4.16(USBDM)
DP: R71.2 U4.15(USBDP)
EZFET_AVBUS: C24.1 R56.1 R61.2 U2.1(P6.0/CB0/A0)
EZFET_AVCC2ADC: C22.1 R55.1 R60.2 U2.2(P6.1/CB1/A1)
EZFET_D_N: C42.1 R72.2 U2.52(PU.1/DM)
EZFET_D_P: C43.1 R75.2 R76.1 R77.2 U2.50(PU.0/DP)
EZFET_LED0: R58.2 U2.20(P1.2/TA0.1)
EZFET_LED1: R59.2 U2.21(P1.3/TA0.2)
EZFET_PUR: R76.2 U2.51(PUR)
EZFET_RST: C23.1 J9.11 R57.1 U2.64(~{RST}/NMI/SBWTDIO)
EZFET_TCK: J9.7 U2.63(PJ.3/TCK)
EZFET_TDI: J9.3 U2.61(PJ.1/TDI/TCLK)
EZFET_TDO: J9.1 U2.60(PJ.0/TDO)
EZFET_TEST: J9.8 U2.59(TEST/SBWTCK)
EZFET_TMS: J9.5 U2.62(PJ.2/TMS)
EZFET_UARTRXD: R66.1 R70.2 U2.38(P3.4/UCA0RXD/UCA0SOMI)
EZFET_UARTTXD: R67.1 R69.1 U2.37(P3.3/UCA0TXD/UCA0SIMO)
EZFET_USB_Shield: C47.1 J11.6 J11.7 J11.8 J11.9 J11.10 J11.11 R78.2
EZFET_V18: C28.1 U2.55(V18)
EZFET_VCORE: C29.1 U2.17(VCORE)
EZFET_VREF: C25.1 U2.9(P5.0/A8/VREF+/VEREF+)
EZFET_VUSB: C30.1 U2.54(VUSB)
EZFET_XT2IN: U2.57(P5.2/XT2IN) Y1.1(In)
EZFET_XT2OUT: U2.58(P5.3/XT2OUT) Y1.3(Out)
MCU_UARTRXD: J10.8 ; off-sheet MCU_UARTRXD
MCU_UARTTXD: J10.6 ; off-sheet MCU_UARTTXD
RST/SBWTDIO: J10.4 ; off-sheet RST/SBWTDIO
RX: R70.1 U4.5(RXD)
T_RST_RST: R65.1 U2.43(P4.2/PM_UCB1SOMI/PM_UCB1SCL)
T_TEST_TCKC: R64.1 U2.44(P4.3/PM_UCB1CLK/PM_UCA1STE)
TST/SBWTCK: J10.2 ; off-sheet TST/SBWTCK
TX: R69.2 U4.1(TXD)
USB_D_N: J11.2(D-) R72.1 R73.1 U6.2(NC) U6.6(IO2)
USB_D_P: J11.3(D+) R71.1 R75.1 U6.3(IO1)
NetC26_2: C26.2 J10.1 R64.2
NetC27_2: C27.2 J10.3 R65.2
NetC38_1: C38.1 C40.1 R68.1 U3.1(OUT)
NetC39_1: C39.1 U3.3(NR)
NetC45_1: C45.1 R74.1 U5.1(OUT)
NetC46_1: C46.1 U5.8(MID_OUT)
NetD1_2: D1.2(A) R58.1
NetD2_2: D2.2(A) R59.1
NetD3_2: D3.2(A) L1.2
NetJ9_2: J9.2 R63.2
NetJ9_4: J9.4 R62.2
NetJ10_5: J10.5 R66.2
NetJ10_7: J10.7 R67.2
NetJ11_1: J11.1(VBUS) L1.1
NetJ11_5: J11.5(GND) L2.1

Not connected (* = marked no-connect by the designer): J9 6* 10* 12* 13* 14*; J10 11* 12*; J11 4(ID)*; U2 3(P6.2/CB2/A2) 4(P6.3/CB3/A3) 5(P6.4/CB4/A4) 6(P6.5/CB5/A5) 7(P6.6/CB6/A6) 8(P6.7/CB7/A7) 10(P5.1/A9/VREF-/VEREF-) 12(P5.4/XIN) 13(P5.5/XOUT) 18(P1.0/TA0CLK/ACLK) 19(P1.1/TA0.0) 22(P1.4/TA0.3) 23(P1.5/TA0.4) 24(P1.6/TA1CLK/CBOUT) 25(P1.7/TA1.0) 26(P2.0/TA1.1) 27(P2.1/TA1.2) 28(P2.2/TA2CLK/SMCLK) 29(P2.3/TA2.0) 30(P2.4/TA2.1) 31(P2.5/TA2.2) 32(P2.6/RTCCLK/DMAE0)* 33(P2.7/UCB0STE/UCA0CLK)* 34(P3.0/UCB0SIMO/UCB0SDA) 35(P3.1/UCB0SOMI/UCB0SCL) 36(P3.2/UCB0CLK/UCA0STE) 41(P4.0/PM_UCB1STE/PM_UCA1CLK) 42(P4.1/PM_UCB1SIMO/PM_UCB1SDA) 45(P4.4/PM_UCA1TXD/PM_UCA1SIMO)* 46(P4.5/PM_UCA1RXD/PM_UCA1SOMI) 47(P4.6/PM_NONE) 48(P4.7/PM_NONE); U3 2(NC)* 6(NC)* 7(NC)*; U4 2(~{DTR})* 3(~{RTS})* 6(~{RI})* 8(NC)* 9(~{DSR})* 10(~{DCD})* 11(~{CTS})* 12(CBUS4)* 13(CBUS2)* 14(CBUS3)* 19(~{RESET})* 22(CBUS1)* 23(CBUS0)* 24(NC)* 27(OSCI)* 28(OSCO)*; U5 3(PG) 6(EN)* 9(NC)*; U6 5(NC)*

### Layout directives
net class Power-Net: EZFET_VBUS, EZFET_VCC, GND, MCU_3V3
differential pair: EZFET_D_N, EZFET_D_P, USB_D_N, USB_D_P

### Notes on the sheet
- (near D1) Host MCU for Emulation
- (near C24) to Host-MCU
- (near R57) Reset Circuit
- to Target-Connector
- (near C20) Place near MSP430
- to Voltage-Divider
- TAG-Connector (Host Debug)
- DNPed Pin 2 zero resistor. If debug or programming adapter is used to power the MSP430, remove Pin 4 resistor and populate Pin 2 resistor.
- (near J9) Host-MCU Debug Connector
- to USB
- to TAG-Connector
- POP Pin 2 zero ohm resistor if FET is supplying 3V3 to MSP430
  POP Pin 4 zero ohm resistor if USB is supplying 3V3 to MSP430 (via LDO)
- Target Connector
- to Host-MCU
- to Target MCU
- 3.3V Power (EZFET_VCC)
- Pins 1, 2
- Pins 3, 4
- (near SH-J25) Pins 5, 6
- (near SH-J26) Pins 7, 8
- (near SH-J28) Pins 11, 12
- (near SH-J29) Pins 13, 14
- (near U4) FTDI regulator used for 3.3V
- USB-Interface
- 3.3V Power backup

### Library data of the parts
C20 = CMP-0006269-2: CAP, CERM, 4.7 uF, 10 V, +/- 20%, X5R, 0402; Manufacturer: TDK; TaMin_C: -55°C; Polarized: N; SizeAreaWB_mm2: 3; Value1: Unknown; U/M: EA; Value: 4.7uF; TaMax_C: 85°C; SizeZ_mm: 0.6; SizeX_mm: 1; SizeY_mm: 0.5; Cap_F: 4.7µF; AEC Category: Q200
C21 C25 C32-C34 C48 = CMP-0006221-2: CAP, CERM, 0.1 uF, 10 V, +/- 20%, X5R, 0402; Manufacturer: Wurth Elektronik; TaMin_C: -55°C; Polarized: N; SizeAreaWB_mm2: 3; Value1: Unknown; U/M: EA; Value: 0.1uF; TaMax_C: 85°C; SizeZ_mm: 0.6; SizeX_mm: 1; SizeY_mm: 0.5; Cap_F: 100nF; AEC Category: Q200
C22 C24 = CMP-0097306-1: 33 pF ±5% 50V Ceramic Capacitor C0G, NP0 0402 (1005 Metric); Manufacturer: Wurth Electronics; AEC Qualified: No; Value: 33pF; TempCo: 30ppm/°C; SizeZ_mm: 0.55mm
C23 = CMP-0006231-2: CAP, CERM, 1000 pF, 50 V, +/- 10%, X7R, 0402; Manufacturer: Wurth Elektronik; TaMin_C: -55°C; Polarized: N; SizeAreaWB_mm2: 3; Value1: Unknown; U/M: EA; Value: 1000pF; TaMax_C: 125°C; SizeZ_mm: 0.6; SizeX_mm: 1; SizeY_mm: 0.5; Cap_F: 1nF; AEC Category: Q200
C26 C27 C42 C43 = CMP-0006215-2: CAP, CERM, 10 pF, 50 V, +/- 5%, C0G/NP0, 0402; Manufacturer: Wurth Elektronik; TaMin_C: -55°C; Polarized: N; SizeAreaWB_mm2: 3; Value1: Unknown; U/M: EA; Value: 10pF; TaMax_C: 125°C; SizeZ_mm: 0.6; SizeX_mm: 1; SizeY_mm: 0.5; AEC Category: Q200
C28 C30 C47 = CMP-0078875-1: CAP, CERM, 0.22 µF, 10 V,+/- 20%, X5R, 0402; Manufacturer: Wurth Elektronik; TaMin_C: -55°C; Polarized: N; SizeAreaWB_mm2: 3; U/M: EA; Value: 0.22uF; TaMax_C: 85°C; SizeZ_mm: 0.6; SizeX_mm: 1; SizeY_mm: 0.5; Cap_F: 220nF; AEC Category: Q200
C29 = CMP-0097299-1: 0.47 µF ±20% 10V Ceramic Capacitor X5R 0603 (1608 Metric); Manufacturer: Wurth Electronics; Value: 470nF; AEC Qualified: No; TempCo: 15%; SizeZ_mm: 0.87mm
C31 = CMP-0084376-1: CAP, Tantalum Polymer, 10 µF, 10 V,+/- 20%, 0.08 ohm, 3216-18 SMD; Manufacturer: Kemet; TaMin_C: -55°C; SizeArea_mm2: 5.12; Value: 10uF; SizeAreaWB_mm2: 10.92; SizeY_mm: 1.6; Polarized: Y; SizeX_mm: 3.2; AEC Qualified: N; TaMax_C: 105°C; SizeZ_mm: 1.8; ESR_ohm: 80m; CompType: Capacitor; AEC Category: Q200
C35 C40 C45 = CMP-0064924-2: CAP, CERM, 1 uF, 10 V,+/- 20%, X5R, 0402; Manufacturer: Wurth Elektronik; TaMin_C: -55°C; Polarized: N; SizeAreaWB_mm2: 3; Value1: Unknown; U/M: EA; Value: 1uF; TaMax_C: 85°C; SizeZ_mm: 0.6; SizeX_mm: 1; SizeY_mm: 0.5; Cap_F: 1µF; AEC Category: Q200
C36 = CMP-0006562-2: CAP, CERM, 0.1 uF, 10 V, +/- 10%, X5R, 0402; Manufacturer: MuRata; TaMin_C: -55°C; Polarized: N; SizeAreaWB_mm2: 3; Value1: Unknown; U/M: EA; Value: 0.1uF; TaMax_C: 85°C; SizeZ_mm: 0.6; SizeX_mm: 1; SizeY_mm: 0.5; Cap_F: 100nF; AEC Category: Q200
C37 C39 = CMP-0006639-2: CAP, CERM, 0.01 uF, 16 V, +/- 10%, X7R, 0402; Manufacturer: MuRata; TaMin_C: -55°C; Polarized: N; SizeAreaWB_mm2: 3; Value1: Unknown; U/M: EA; Value: 0.01uF; TaMax_C: 125°C; SizeZ_mm: 0.6; SizeX_mm: 1; SizeY_mm: 0.5; Cap_F: 10nF; AEC Category: Q200
C38 = CMP-0006594-2: CAP, CERM, 2.2 uF, 16 V, +/- 10%, X5R, 0402; Manufacturer: MuRata; TaMin_C: -55°C; Polarized: N; SizeAreaWB_mm2: 3; Value1: Unknown; U/M: EA; Value: 2.2uF; TaMax_C: 85°C; SizeZ_mm: 0.6; SizeX_mm: 1; SizeY_mm: 0.5; Value2: 16V; Cap_F: 2.2µF; AEC Category: Q200
C41 = CMP-0006221-2: CAP, CERM, 0.1 uF, 10 V, +/- 20%, X5R, 0402; Manufacturer: Wurth Elektronik; Value: 0.1uF; Polarized: N; U/M: EA; Cap_F: 100nF; Value1: Unknown; VDC_V: 10V; TaMin_C: -55°C; TaMax_C: 85°C; AEC Category: Q200; SizeArea_mm2: 0.5; SizeAreaWB_mm2: 3; SizeX_mm: 1; SizeZ_mm: 0.6
C44 = CMP-14477-003474-2: None; Dielectric: X5R; Tolerance: 20%
C46 = CMP-0008271-1: CAP, CERM, 3.3 uF, 25 V, +/- 10%, X6S, 0805; Manufacturer: MuRata; TaMin_C: -55°C; Polarized: N; SizeAreaWB_mm2: 6.75; Value1: Unknown; U/M: EA; Value: 3.3uF; TaMax_C: 105°C; SizeZ_mm: 1.45; SizeX_mm: 2; SizeY_mm: 1.25; Cap_Case: 0805; SizeArea_mm2: 2.5; Cap_F: 3.3µF; AEC Category: Q200
D1 = CMP-0002947-3: LED, Red, SMD; Manufacturer: Wurth Elektronik; Type: AlInGaP; Vf_V: 2V; Io_A: 30mA; Vr_V: 5V; Tjmax_C: 85°C; Power_TotalModule: 72mW; Value1: 0.072W; Angle: 140
D2 = CMP-0002894-2: LED, Green, SMD; Manufacturer: Wurth Elektronik; Type: AlInGaP; Vf_V: 2V; Io_A: 20mA; Value1: W
D3 = CMP-1055-00457-1: Schottky Barrier Diode, 2-Pin SOD-323, Pb-Free, Tape and Reel; Manufacturer: On Semiconductor; Configuration: Single
J9 J10 = CMP-0086014-1: Header, 2.54mm, 7x2, Gold, TH; Manufacturer: Wurth Elektronik; Pitch_mm: 2.54; Voltage_V: 250V; Shrouded: N; Gender: Male; Current_A: 3A; Cert_UL: Y; Row_Count: 2
J11 = CMP-0055311-1: Receptacle, USB 2.0, Micro B, 5 Position, R/A, SMT; Manufacturer: Molex; Pitch_mm: 0.65; Gender: Female; ContactFinish: Gold; Current_A: 1.8A; Voltage_V: 30V; Cert_UL: Y; CNHeader: FALSE; CT: TRUE
L1 = CMP-0081962-1: Ferrite Bead, 150 ohm @ 100 MHz, 0.7 A, 0603; Manufacturer: MuRata; SizeAreaWB_mm2: 4.68; SizeArea_mm2: 1.28; SizeZ_mm: 1; Imax_A: 700mA; ZTyp@100MHz_Ohm: 150; SizeY_mm: 0.8; Value2: 0.7A; Value1: 0.35 ohm; DCR_ohm: 0.35; SizeX_mm: 1.6
L2 = CMP-0081962-1: Ferrite Bead, 150 ohm @ 100 MHz, 0.7 A, 0603; Manufacturer: MuRata; SizeAreaWB_mm2: 4.68; SizeArea_mm2: 1.28; Value: 150 ohm; SizeZ_mm: 1; Imax_A: 700mA; ZTyp@100MHz_Ohm: 150; SizeY_mm: 0.8; Value2: 0.7A; Value1: 0.35 ohm; DCR_ohm: 0.35; SizeX_mm: 1.6
R55 R60 = CMP-0026728-1: RES, 220 k, 1%, 0.0625 W, 0402; Manufacturer: Yageo America; Power_W: 62.5mW; TempCo: 100 ppm/C; U/M: EA; Value: 220k; SizeX_mm: 1; SizeY_mm: 0.5; SizeZ_mm: 0.6; AEC Qualified: N; VDC_V: 50V; AEC Category: Q200
R56 = CMP-0026190-2: RES, 240 k, 1%, 0.063 W, AEC-Q200 Grade 0, 0402; Manufacturer: Vishay-Dale; Power_W: 63mW; TempCo: 100 ppm/C; Value: 240k; SizeX_mm: 1; SizeY_mm: 0.5; SizeZ_mm: 0.6; Value2: 0.063W; AEC Qualified: Y; VDC_V: 50V; AEC Category: Q200; AEC Grade: 0
R57 = CMP-0026935-3: as R97 on sheet MD041_Motor_Driver_RevA
R58 = CMP-0026934-3: RES, 470, 5%, 0.063 W, AEC-Q200 Grade 0, 0402; Manufacturer: Vishay-Dale; Value: 470; Value_Code: 470R; Power_W: 63mW; Value2: 0.063W; VDC_V: 50V; TempCo: 200 ppm/C; SizeArea_mm2: 0.5; SizeX_mm: 1; SizeZ_mm: 0.6; EIA_Code: E24; AEC Category: Q200; AEC Qualified: Y; AEC Grade: 0
R59 = CMP-0026948-3: RES, 560, 5%, 0.063 W, AEC-Q200 Grade 0, 0402; Manufacturer: Vishay-Dale; Power_W: 63mW; TempCo: 200 ppm/C; Value_Code: 560R; Value: 560; EIA_Code: E24; SizeX_mm: 1; SizeY_mm: 0.5; SizeZ_mm: 0.6; Value2: 0.063W; AEC Qualified: Y; VDC_V: 50V; AEC Category: Q200; AEC Grade: 0
R61 = CMP-0026021-3: RES, 150 k, 1%, 0.063 W, AEC-Q200 Grade 0, 0402; Manufacturer: Vishay-Dale; Power_W: 63mW; TempCo: 100 ppm/C; Value: 150k; EIA_Code: E96; SizeX_mm: 1; SizeY_mm: 0.5; SizeZ_mm: 0.6; Value2: 0.063W; AEC Qualified: Y; VDC_V: 50V; AEC Category: Q200; AEC Grade: 0
R62 R63 = CMP-0026992-3: RES, 0, 5%, 0.1 W, AEC-Q200 Grade 0, 0402; Manufacturer: Panasonic; Value_Code: 0000; Power_W: 100mW; Value2: 0.1W; VDC_V: 50V; TempCo: 600 ppm/C; EIA_Code: E24; AEC Category: Q200; AEC Qualified: Y; SizeArea_mm2: 0.5; SizeAreaWB_mm2: 3; SizeX_mm: 1; SizeZ_mm: 0.6
R64-R67 = CMP-0025963-3: RES, 10.0, 1%, 0.063 W, AEC-Q200 Grade 0, 0402; Manufacturer: Vishay-Dale; Power_W: 63mW; TempCo: 100 ppm/C; Value_Code: 10R0; Value: 10.0; EIA_Code: E96; Res_ohm: 10; SizeX_mm: 1; SizeY_mm: 0.5; SizeZ_mm: 0.6; Value2: 0.063W; AEC Qualified: Y; VDC_V: 50V; AEC Category: Q200; AEC Grade: 0
R68 = CMP-0026992-3: RES, 0, 5%, 0.1 W, AEC-Q200 Grade 0, 0402; Manufacturer: Panasonic; PartNumber: ERJ-2GE0R00X; Value_Code: 0000; Power_W: 100mW; Value2: 0.1W; VDC_V: 50V; TempCo: 600 ppm/C; EIA_Code: E24; AEC Category: Q200; AEC Qualified: Y; SizeArea_mm2: 0.5; SizeAreaWB_mm2: 3; SizeX_mm: 1; SizeZ_mm: 0.6
R69 R70 = CMP-0025697-4: RES, 0, 5%, 0.1 W, AEC-Q200 Grade 0, 0603; PartNumber: CRCW06030000Z0EA; Manufacturer: Vishay-Dale; Value_Code: 0000; Power_W: 100mW; Value2: 0.1W; VDC_V: 75V; TempCo: 200 ppm/C; EIA_Code: E24; AEC Category: Q200; AEC Qualified: Y; SizeArea_mm2: 1.28; SizeX_mm: 1.6; SizeY_mm: 0.8; SizeZ_mm: 1
R71-R73 R75 = CMP-0026888-3: RES, 27, 5%, 0.063 W, AEC-Q200 Grade 0, 0402; Manufacturer: Vishay-Dale; Power_W: 63mW; TempCo: 200 ppm/C; Value_Code: 27R0; Value: 27; EIA_Code: E24; SizeX_mm: 1; SizeY_mm: 0.5; SizeZ_mm: 0.6; Value2: 0.063W; AEC Qualified: Y; VDC_V: 50V; AEC Category: Q200; AEC Grade: 0
R74 = CMP-2002-00429-1: Manufacturer: Panasonic; Part Number: ERJ-2GE0R00X
R76 = CMP-0026085-3: RES, 1.40 k, 1%, 0.063 W, AEC-Q200 Grade 0, 0402; Manufacturer: Vishay-Dale; Power_W: 63mW; TempCo: 100 ppm/C; Value_Code: 1k40; Value: 1.40k; EIA_Code: E96; Res_ohm: 1.4k; SizeX_mm: 1; SizeY_mm: 0.5; SizeZ_mm: 0.6; Value2: 0.063W; AEC Qualified: Y; VDC_V: 50V; AEC Category: Q200; AEC Grade: 0
R77 = CMP-0026859-2: RES, 1.0 M, 5%, 0.063 W, AEC-Q200 Grade 0, 0402; Manufacturer: Vishay-Dale; Power_W: 63mW; TempCo: 200 ppm/C; Value_Code: 1M00; Value: 1.0Meg; EIA_Code: E24; Res_ohm: 1M; SizeX_mm: 1; SizeY_mm: 0.5; SizeZ_mm: 0.6; Value2: 0.063W; AEC Qualified: Y; VDC_V: 50V; AEC Category: Q200; AEC Grade: 0
R78 = CMP-0026907-3: RES, 33 k, 5%, 0.063 W, AEC-Q200 Grade 0, 0402; Manufacturer: Vishay-Dale; Power_W: 63mW; TempCo: 200 ppm/C; Value_Code: 33k0; Value: 33k; EIA_Code: E24; SizeX_mm: 1; SizeY_mm: 0.5; SizeZ_mm: 0.6; Value2: 0.063W; AEC Qualified: Y; VDC_V: 50V; AEC Category: Q200; AEC Grade: 0
SH-J23-SH-J29 = CMP-0003761-2: as SH-J18 on sheet MD041_Motor_Driver_RevA
U2 = CMP-0039269-4: 16-Bit Ultra-Low-Power Microcontroller, 128KB Flash, 8KB RAM, USB, 12Bit ADC, 2 USCIs, 32Bit HW MPY, RGC0064B (VQFN-64); Alternate Manufacturer: Texas Instruments; Alternate PartNumber: MSP430F5528IRGCR; ADC: 12-bit SAR; ADC Channels: 16; Brown Out Reset: Yes; DMA: 3; Flash(KB): 128; Frequency(MHz): 25; GPIO: 47; Multiplier: 32x32; SRAM(B): 8192; Timers - 16-bit: 4; USB: 1; USCI_A (UART/LIN/IrDA/SPI): 2; Rating: Catalog; SizeArea_mm2: 81.0; SizeZ_mm: 1.0; Green_REACh: Passed; AEC Qualified: N; AEC Category: Q200; CompType: IC; Green_Lifecycle: Active; SizeY_mm: 9.0; SizeAreaWB_mm2: 121.0
U3 = CMP-0036328-3: 500mA, Adjustable, Low Quiescent Current, Low-Noise, High-PSRR, Single-Output LDO Regulator, DRB0008A (VSON-8); Manufacturer: Texas Instruments; CompType: IC; Green_Lifecycle: Active; SizeZ_mm: 1.0; Iq(Typ)(mA): 0.04; SizeY_mm: 3.0; SizeAreaWB_mm2: 16.0; SizeArea_mm2: 9.0; AEC Category: Q200; Vout Adj(Max)(V): 3.3; AEC Qualified: N; Accuracy(%): 2; Vin(Max)(V): 6.5; Vdo(Typ)(mV): 280; Iout(Max)(A): 0.5; Green_REACh: Passed; Rating: Catalog; Vin(Min)(V): 2.7
U4 = CMP-0004774-1: USB to Serial UART, SSOP28; Manufacturer: FTDI
U5 = CMP-0090815-1: LDO, Fixed Output, Dual, 3.3V, 10/12/15V, 50mA, Precision Enable, Power-Good, HVSSOP10; Manufacturer: Texas Instruments; Output Type: Fixed,Multi; Max Supply Voltage: 85V; TJmax_C: +125°C; Output Voltage: 3.3/10/12/15V; SizeZ_mm: 1.1mm; Dropout Voltage: 200/800mV; Min Supply Voltage: 4V; Standoff Height: 0.05mm; AEC Qualified: No; Number Of Outputs: 2; Accuracy Percentage: 1%; Nominal Supply Current: 100uA
U6 = CMP-0043099-3: Low-Capacitance 2-Channel +/-15kV ESD Protection Array for High-Speed Data Interfaces, DRY0006A (USON-6); Manufacturer: Texas Instruments; IO Leakage Current(nA): 1; IEC 61000-4-2 Air-Gap(+/- kV): 15; USB High Speed: TRUE; IO Capacitance(Typ)(pF): 1.5; Eco-Plan: Green (RoHS & no Sb/Br); Breakdown Voltage(Min)(V): 11; IEC 61000-4-2 Contact(+/- kV): 8; AEC Category: Q200; AEC Qualified: N; CompType: IC; SizeAreaWB_mm2: 4.9; SizeArea_mm2: 1.45; SizeX_mm: 1.0; SizeZ_mm: 0.6; Rating: Catalog
Y1 = CMP-0085483-1: Oscillator, 4 MHz, 700 ppm, 39 pF, SMD; Manufacturer: MuRata; SizeArea_mm2: 9; Load Capacitance: 39 pF; SizeZ_mm: 1.2; AEC Category: Q200; Frequency Tolerance: 700 ppm; SizeX_mm: 4.5; SizeAreaWB_mm2: 16.5; TaMax_C: 85°C; TaMin_C: -20°C; SizeY_mm: 2; AEC Qualified: N; Frequency_Fixed: 4MHz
